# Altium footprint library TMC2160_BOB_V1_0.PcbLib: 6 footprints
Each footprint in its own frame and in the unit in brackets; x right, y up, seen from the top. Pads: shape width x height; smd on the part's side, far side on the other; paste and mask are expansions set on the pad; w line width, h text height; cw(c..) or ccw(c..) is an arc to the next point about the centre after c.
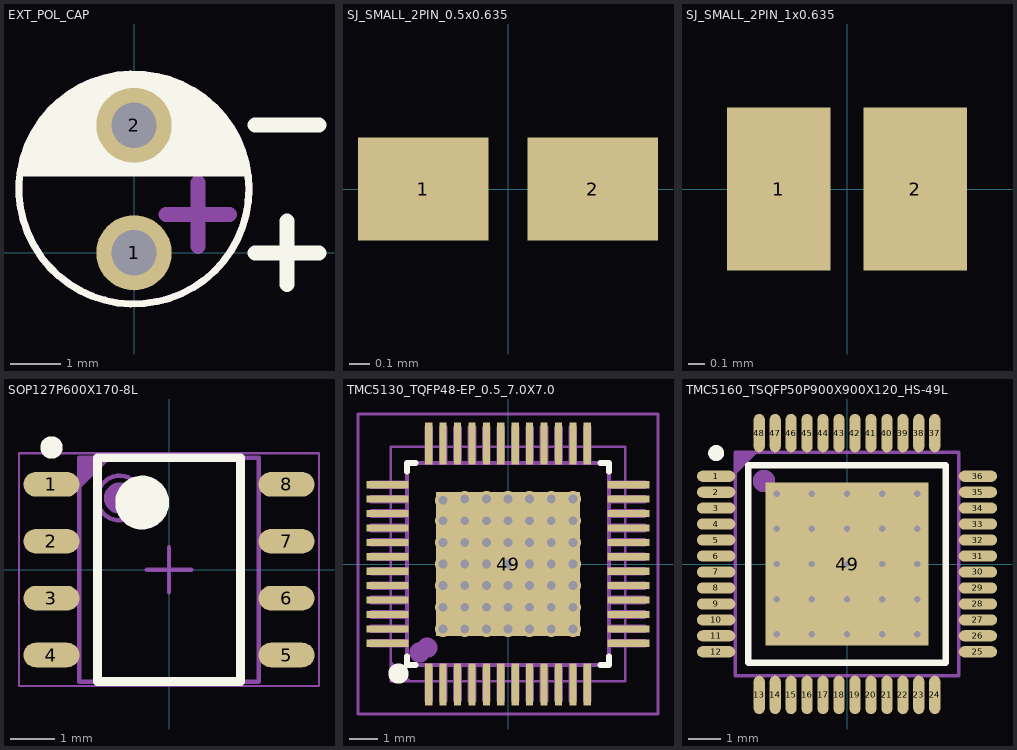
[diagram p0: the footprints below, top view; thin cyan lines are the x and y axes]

## EXT_POL_CAP [mm]
pads (2):
  round 1.5 hole 0.9: 1(0,0) 2(0,2.54)
Top Overlay:
  circle w0.14: c0,1.27 r2.29
  region: 0,1.524 -2.272,1.524 -2.249,1.732 -2.128,2.132 -1.936,2.504 -1.68,2.834 -1.368,3.113 -1.011,3.331 -0.62,3.48 -0.209,3.556 0,3.556 0.209,3.556 0.62,3.48 1.011,3.331 1.368,3.113 1.68,2.834 1.936,2.504 2.128,2.132 2.249,1.732 2.272,1.524 0,1.524 0,1.651 0.087,1.655 0.258,1.689 0.419,1.756 0.564,1.853 0.687,1.976 0.784,2.121 0.851,2.282 0.885,2.453 0.889,2.54 0.885,2.627 0.851,2.798 0.784,2.959 0.687,3.104 0.564,3.227 0.419,3.324 0.258,3.391 0.087,3.425 0,3.429 -0.087,3.425 -0.258,3.391 -0.419,3.324 -0.564,3.227 -0.687,3.104 -0.784,2.959 -0.851,2.798 -0.885,2.627 -0.889,2.54 -0.885,2.453 -0.851,2.282 -0.784,2.121 -0.687,1.976 -0.564,1.853 -0.419,1.756 -0.258,1.689 -0.087,1.655 0,1.651
  pour cut-out: 0.889,2.54 0.889,2.628 0.855,2.799 0.788,2.961 0.691,3.107 0.567,3.231 0.421,3.328 0.259,3.395 0.088,3.429 0,3.429 -0.088,3.429 -0.259,3.395 -0.421,3.328 -0.567,3.231 -0.691,3.107 -0.788,2.961 -0.855,2.799 -0.889,2.628 -0.889,2.54 -0.889,2.452 -0.855,2.281 -0.788,2.119 -0.691,1.973 -0.567,1.849 -0.421,1.752 -0.259,1.685 -0.088,1.651 0,1.651 0.088,1.651 0.259,1.685 0.421,1.752 0.567,1.849 0.691,1.973 0.788,2.119 0.855,2.281 0.889,2.452
  lines w0.3: 2.413,0 3.683,0 ; 2.413,2.54 3.683,2.54 ; 3.048,-0.635 3.048,0.635
TopAsm:
  circle w0.14: c0,1.27 r2.29
  region: -2.254,1.651 2.258,1.651 2.224,1.849 2.089,2.228 1.89,2.577 1.633,2.886 1.326,3.146 0.978,3.348 0.6,3.486 0.205,3.556 0.004,3.556 -0.198,3.556 -0.594,3.486 -0.972,3.348 -1.32,3.146 -1.627,2.887 -1.885,2.578 -2.085,2.228 -2.22,1.849
  lines w0.3: 0.635,0.762 1.905,0.762 ; 1.27,0.127 1.27,1.397
  text ".Designator" at -1.905,0.762 h1.27

## SJ_SMALL_2PIN_0.5x0.635 [mm]
pads (2):
  rect 0.635x0.5 smd: 1(-0.413,0) 2(0.413,0)

## SJ_SMALL_2PIN_1x0.635 [mm]
pads (2):
  rect 0.635x1 smd: 1(-0.419,0) 2(0.419,0)

## SOP127P600X170-8L [mm] "SOP, 8-Leads, Body 4,90x3,90mm, Pitch 1,27mm, IPC High Density"
height 1.7
pads (8):
  oval 1.25x0.55 smd: 1(-2.625,1.905) 2(-2.625,0.635) 3(-2.625,-0.635) 4(-2.625,-1.905) 5(2.625,-1.905) 6(2.625,-0.635) 7(2.625,0.635) 8(2.625,1.905)
Top Overlay:
  circle w0.6: c-0.6,1.5 r0.3
  circle w0.25: c-2.625,2.73 r0.125
  lines w0.2: -1.6,-2.5 1.6,-2.5 1.6,2.5 -1.6,2.5 -1.6,-2.5
Mechanical 13:
  circle w0.1: c-1.1,1.6 r0.5
  lines w0.1: -2,-2.5 -2,2.5 2,2.5 2,-2.5 -2,-2.5
Mechanical 15:
  lines w0.05: -3.35,-2.6 3.35,-2.6 3.35,2.6 -3.35,2.6 -3.35,-2.6
  lines w0.1: -0.5,0 0.5,0 ; 0,-0.5 0,0.5
TopAsm:
  circle w0.5: c-1.1,1.6 r0.1
  region: -1.294,2.5 -2,1.794 -2,2.5
  lines w0.1: -2,-2.5 2,-2.5 2,2.5 -2,2.5 -2,-2.5
  text ".Designator" at 0.635,-1.905 h1.27
3D body "SOP127P600X170-8L.step": height 1.7, standoff 0, extent -3,-2.5 3,2.5

## TMC5130_TQFP48-EP_0.5_7.0X7.0 [mm]
pads (49):
  rect 0.25x1.45 smd: 1(-2.75,-4.175) 2(-2.25,-4.175) 3(-1.75,-4.175) 4(-1.25,-4.175) 5(-0.75,-4.175) 6(-0.25,-4.175) 7(0.25,-4.175) 8(0.75,-4.175) 9(1.25,-4.175) 10(1.75,-4.175) 11(2.25,-4.175) 12(2.75,-4.175) 25(2.75,4.175) 26(2.25,4.175) 27(1.75,4.175) 28(1.25,4.175) 29(0.75,4.175) 30(0.25,4.175) 31(-0.25,4.175) 32(-0.75,4.175) 33(-1.25,4.175) 34(-1.75,4.175) 35(-2.25,4.175) 36(-2.75,4.175)
  rect 1.45x0.25 smd: 13(4.175,-2.75) 14(4.175,-2.25) 15(4.175,-1.75) 16(4.175,-1.25) 17(4.175,-0.75) 18(4.175,-0.25) 19(4.175,0.25) 20(4.175,0.75) 21(4.175,1.25) 22(4.175,1.75) 23(4.175,2.25) 24(4.175,2.75) 37(-4.175,2.75) 38(-4.175,2.25) 39(-4.175,1.75) 40(-4.175,1.25) 41(-4.175,0.75) 42(-4.175,0.25) 43(-4.175,-0.25) 44(-4.175,-0.75) 45(-4.175,-1.25) 46(-4.175,-1.75) 47(-4.175,-2.25) 48(-4.175,-2.75)
  rrect0% 5x5 smd paste-254: 49(0,0)
via 0,-1.5 diameter 0.559 hole 0.305
via -0.75,-1.5 diameter 0.559 hole 0.305
via -1.5,-1.5 diameter 0.559 hole 0.305
via -2.25,-1.5 diameter 0.559 hole 0.305
via 0.75,-1.5 diameter 0.559 hole 0.305
via 1.5,-1.5 diameter 0.559 hole 0.305
via 2.25,-1.5 diameter 0.559 hole 0.305
via 0,-0.75 diameter 0.559 hole 0.305
via -0.75,-0.75 diameter 0.559 hole 0.305
via -1.5,-0.75 diameter 0.559 hole 0.305
via -2.25,-0.75 diameter 0.559 hole 0.305
via 0.75,-0.75 diameter 0.559 hole 0.305
via 1.5,-0.75 diameter 0.559 hole 0.305
via 2.25,-0.75 diameter 0.559 hole 0.305
via 0,2.25 diameter 0.559 hole 0.305
via -0.75,2.25 diameter 0.559 hole 0.305
via -1.5,2.25 diameter 0.559 hole 0.305
via 0.75,2.25 diameter 0.559 hole 0.305
via 1.5,2.25 diameter 0.559 hole 0.305
via 2.25,2.25 diameter 0.559 hole 0.305
via 0,1.5 diameter 0.559 hole 0.305
via -0.75,1.5 diameter 0.559 hole 0.305
via -1.5,1.5 diameter 0.559 hole 0.305
via -2.25,1.5 diameter 0.559 hole 0.305
via 0.75,1.5 diameter 0.559 hole 0.305
via 1.5,1.5 diameter 0.559 hole 0.305
via 2.25,1.5 diameter 0.559 hole 0.305
via 0,0.75 diameter 0.559 hole 0.305
via -0.75,0.75 diameter 0.559 hole 0.305
via -1.5,0.75 diameter 0.559 hole 0.305
via -2.25,0.75 diameter 0.559 hole 0.305
via 0.75,0.75 diameter 0.559 hole 0.305
via 1.5,0.75 diameter 0.559 hole 0.305
via 2.25,0.75 diameter 0.559 hole 0.305
via 2.25,0 diameter 0.559 hole 0.305
via 1.5,0 diameter 0.559 hole 0.305
via 0.75,0 diameter 0.559 hole 0.305
via -2.25,0 diameter 0.559 hole 0.305
via -1.5,0 diameter 0.559 hole 0.305
via -0.75,0 diameter 0.559 hole 0.305
via 0,0 diameter 0.559 hole 0.305
via 0,-2.25 diameter 0.559 hole 0.305
via 0.75,-2.25 diameter 0.559 hole 0.305
via 2.25,-2.25 diameter 0.559 hole 0.305
via 1.5,-2.25 diameter 0.559 hole 0.305
via -1.5,-2.25 diameter 0.559 hole 0.305
via -0.75,-2.25 diameter 0.559 hole 0.305
via -2.25,-2.25 diameter 0.559 hole 0.305
via -2.256,2.207 diameter 0.559 hole 0.305
Top Overlay:
  circle w0.5: c-3.8,-3.8 r0.1
  lines w0.2: -3.5,-3.2 -3.5,-3.5 -3.2,-3.5 ; -3.5,3.2 -3.5,3.5 -3.2,3.5 ; 3.2,-3.5 3.5,-3.5 3.5,-3.2 ; 3.2,3.5 3.5,3.5 3.5,3.2
Top Paste:
  region: -2.4,2.4 -0.4,2.4 -0.4,0.4 -2.4,0.4
  region: -2.4,-0.4 -0.4,-0.4 -0.4,-2.4 -2.4,-2.4
  region: 0.4,-0.4 2.4,-0.4 2.4,-2.4 0.4,-2.4
  region: 0.4,2.4 2.4,2.4 2.4,0.4 0.4,0.4
Bottom Solder:
  region: -2.54,2.54 -2.54,-2.54 2.54,-2.54 2.54,2.54
Mechanical 13:
  drawing of 197 lines, arcs and shapes, not listed
Mechanical 15:
  lines w0.1: -5.2,-5.2 5.2,-5.2 5.2,5.2 -5.2,5.2 -5.2,-5.2
TopAsm:
  circle w0.5: c-3.064,-3.064 r0.1
  region: -4.064,-3.358 -3.358,-4.064 -4.064,-4.064
  lines w0.076: -4.064,-4.064 4.064,-4.064 4.064,4.064 -4.064,4.064 -4.064,-4.064
  text ".Designator" at -3.302,-0.508 h1.27
3D body: height 1, standoff 0.05, extent -3.5,-3.5 3.5,3.5

## TMC5160_TSQFP50P900X900X120_HS-49L [mm] "TSQFP, 48-Leads, Body 7,00x7,00mm, Pitch 0,50mm, Thermal Pad 5,10x5,10mm, IPC High Density"
height 1.2
pads (49):
  oval 1.2x0.35 smd mask+0.102: 1(-4.1,2.75) 2(-4.1,2.25) 3(-4.1,1.75) 4(-4.1,1.25) 5(-4.1,0.75) 6(-4.1,0.25) 7(-4.1,-0.25) 8(-4.1,-0.75) 9(-4.1,-1.25) 10(-4.1,-1.75) 11(-4.1,-2.25) 12(-4.1,-2.75) 25(4.1,-2.75) 26(4.1,-2.25) 27(4.1,-1.75) 28(4.1,-1.25) 29(4.1,-0.75) 30(4.1,-0.25) 31(4.1,0.25) 32(4.1,0.75) 33(4.1,1.25) 34(4.1,1.75) 35(4.1,2.25) 36(4.1,2.75)
  oval 0.35x1.2 smd mask+0.102: 13(-2.75,-4.1) 14(-2.25,-4.1) 15(-1.75,-4.1) 16(-1.25,-4.1) 17(-0.75,-4.1) 18(-0.25,-4.1) 19(0.25,-4.1) 20(0.75,-4.1) 21(1.25,-4.1) 22(1.75,-4.1) 23(2.25,-4.1) 24(2.75,-4.1) 37(2.75,4.1) 38(2.25,4.1) 39(1.75,4.1) 40(1.25,4.1) 41(0.75,4.1) 42(0.25,4.1) 43(-0.25,4.1) 44(-0.75,4.1) 45(-1.25,4.1) 46(-1.75,4.1) 47(-2.25,4.1) 48(-2.75,4.1)
  rect 5.1x5.1 smd: 49(0,0)
via -2.2,2.2 diameter 0.5 hole 0.2
via -1.1,2.2 diameter 0.5 hole 0.2
via 0,2.2 diameter 0.5 hole 0.2
via 1.1,2.2 diameter 0.5 hole 0.2
via 2.2,2.2 diameter 0.5 hole 0.2
via -2.2,1.1 diameter 0.5 hole 0.2
via -1.1,1.1 diameter 0.5 hole 0.2
via 0,1.1 diameter 0.5 hole 0.2
via 1.1,1.1 diameter 0.5 hole 0.2
via 2.2,1.1 diameter 0.5 hole 0.2
via -2.2,0 diameter 0.5 hole 0.2
via -1.1,0 diameter 0.5 hole 0.2
via 0,0 diameter 0.5 hole 0.2
via 1.1,0 diameter 0.5 hole 0.2
via 2.2,0 diameter 0.5 hole 0.2
via -2.2,-1.1 diameter 0.5 hole 0.2
via -1.1,-1.1 diameter 0.5 hole 0.2
via 0,-1.1 diameter 0.5 hole 0.2
via 1.1,-1.1 diameter 0.5 hole 0.2
via 2.2,-1.1 diameter 0.5 hole 0.2
via -2.2,-2.2 diameter 0.5 hole 0.2
via -1.1,-2.2 diameter 0.5 hole 0.2
via 0,-2.2 diameter 0.5 hole 0.2
via 1.1,-2.2 diameter 0.5 hole 0.2
via 2.2,-2.2 diameter 0.5 hole 0.2
Top Overlay:
  circle w0.25: c-4.1,3.475 r0.125
  lines w0.2: -3.1,-3.1 -3.1,3.1 3.1,3.1 3.1,-3.1 -3.1,-3.1
Bottom Solder:
  region: -2.54,2.54 -2.54,-2.54 2.54,-2.54 2.54,2.54
TopAsm:
  circle w0.5: c-2.6,2.6 r0.1
  region: -2.794,3.5 -3.5,2.794 -3.5,3.5
  lines w0.1: -3.5,-3.5 3.5,-3.5 3.5,3.5 -3.5,3.5 -3.5,-3.5
  text ".Designator" at -2.413,-0.381 h1.27
3D body "TSQFP50P900X900X120_HS-49L.step": height 1.2, standoff 0, extent -4.5,-4.5 4.5,4.5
